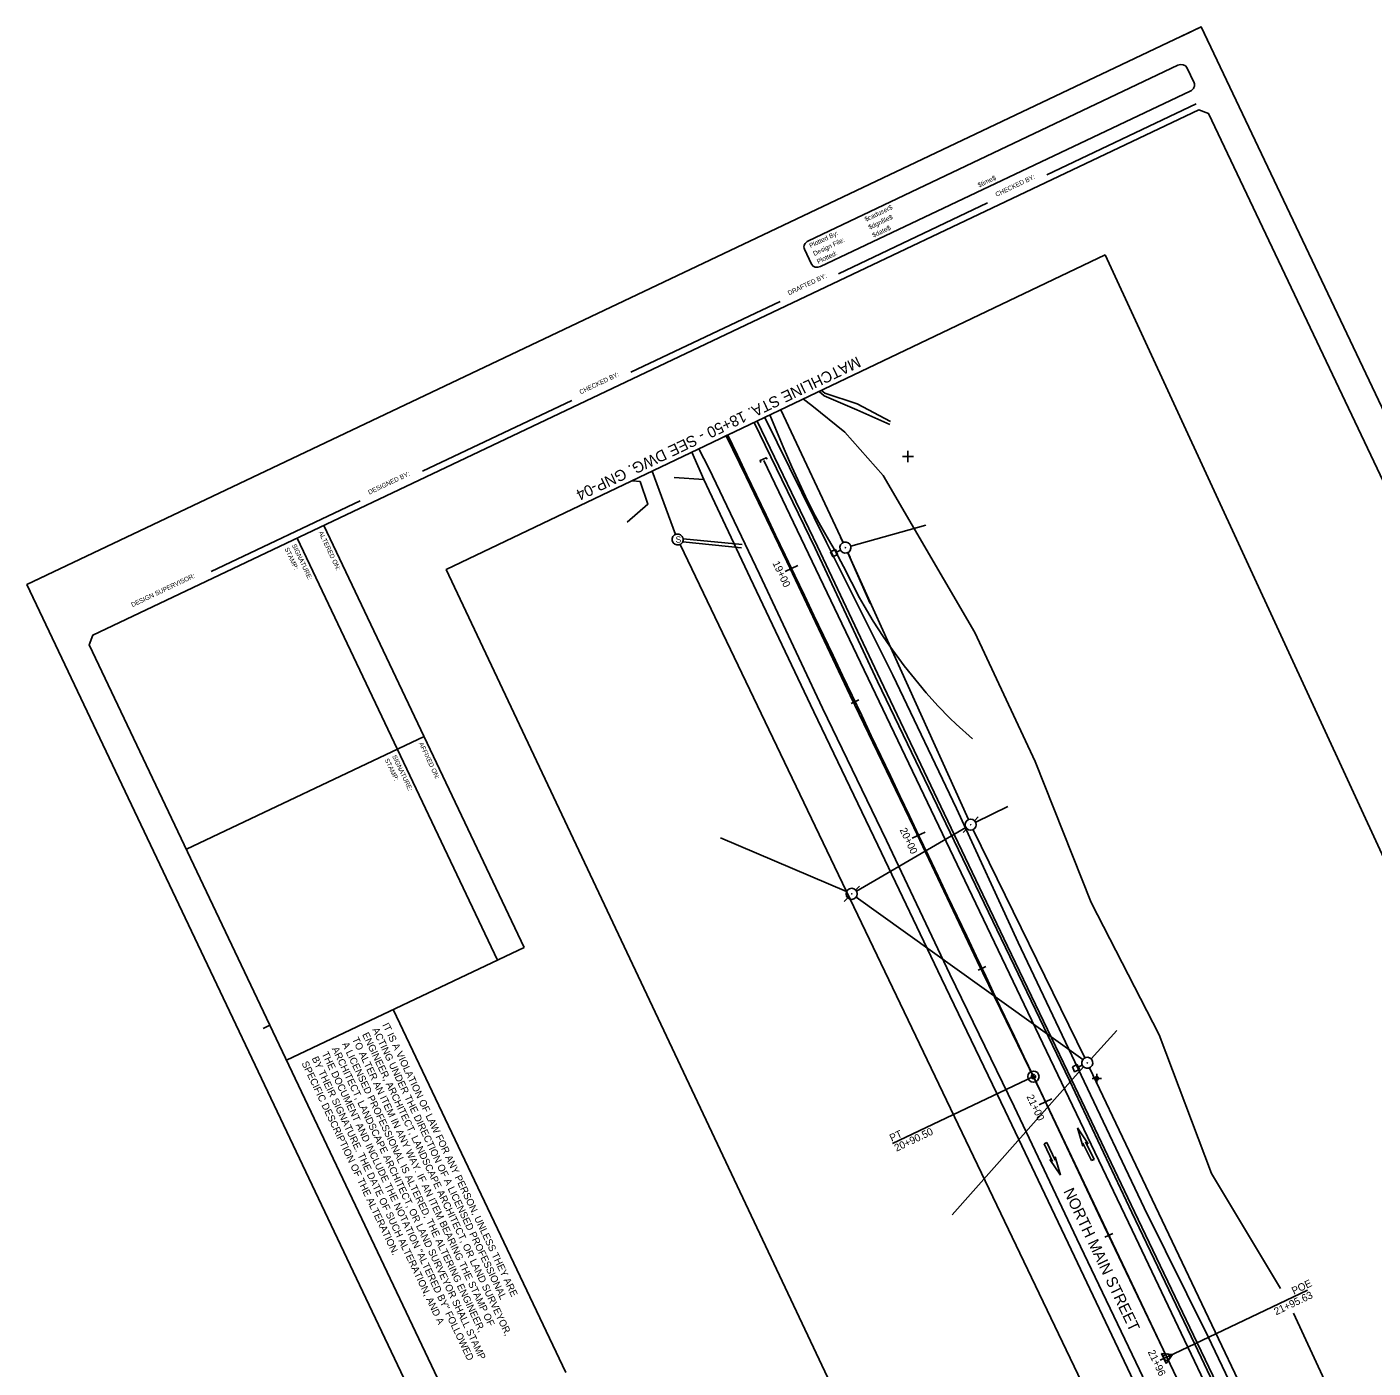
# Model space of a CAD drawing. Extents: x 1041072 to 1041761, y 1125784 to 1126587.
# Drawn here: x 1041071.6 to 1041527.2, y 1126132.8 to 1126586.8 of the extents above; entities that cross this region are included whole.
import ezdxf

# ---------------------------------------------------------------- set-up
doc = ezdxf.new("R2010")
doc.units = 0
for name, color, linetype in [('AC_P', 7, 'Continuous'), ('ACP_P', 7, 'Continuous'), ('ACSC_P_T', 7, 'Continuous'), ('ACSCT_P', 7, 'Continuous'), ('ACSR_P_T', 7, 'Continuous'), ('ACSRT_P', 7, 'Continuous'), ('clip boundary', 7, 'Continuous'), ('Default', 7, 'Continuous'), ('EWFG', 7, 'Continuous'), ('LAWA', 7, 'Continuous'), ('LAWE', 7, 'Continuous'), ('LELB', 7, 'Continuous'), ('NBS_P', 7, 'Continuous'), ('NBS_P_T', 7, 'Continuous'), ('NML_P', 7, 'Continuous'), ('NML_P_T', 7, 'Continuous'), ('O_Details_Text Title and Subtitle Proposed_P_T', 7, 'Continuous'), ('PE', 7, 'Continuous'), ('PELB', 7, 'Continuous'), ('PSU', 7, 'Continuous'), ('RGB', 7, 'Continuous'), ('S', 7, 'Continuous'), ('SHEET_BORDER', 7, 'Continuous'), ('SHEET_BORDER_CUT', 7, 'Continuous'), ('SHEET_BORDER_STAMPBOX', 7, 'Continuous'), ('SHEET_BORDER_TEXT', 7, 'Continuous'), ('STDSW', 7, 'Continuous'), ('STDSY', 7, 'Continuous'), ('STFBY', 7, 'Continuous'), ('STSEW', 7, 'Continuous'), ('STSEY_P_T', 7, 'Continuous'), ('UEO', 7, 'Continuous'), ('UG', 7, 'Continuous'), ('UP', 7, 'Continuous'), ('UPGW', 7, 'Continuous'), ('UPL', 7, 'Continuous'), ('USA', 7, 'Continuous'), ('USMH', 7, 'Continuous')]:
    doc.layers.add(name, color=color, linetype=linetype)

msp = doc.modelspace()

# ---------------------------------------------------------------- linework, layer by layer
at = {"layer": 'AC_P'}
msp.add_line((1041412.24, 1126231.51), (1041457.34, 1126136.54), dxfattribs=at)
msp.add_arc((951081.07, 1083333.02), 100000, 25.4031549, 25.5409537, dxfattribs=at)
at = {"layer": 'ACP_P'}
for centre, radius in [((1041412.24, 1126231.5), 1.89), ((1041412.24, 1126231.5), 0.744), ((1041412.24, 1126231.5), 0.154), ((1041457.34, 1126136.54), 1.09)]:
    msp.add_circle(centre, radius, dxfattribs=at)
at = {"layer": 'ACSCT_P'}
for points in [[(1041412.24, 1126231.51), (1041364.55, 1126208.86)], [(1041457.34, 1126136.54), (1041505.03, 1126159.19)]]:
    msp.add_lwpolyline(points, dxfattribs=at)
at = {"layer": 'ACSRT_P'}
for points in [[(1041310.11, 1126449.25), (1041307.51, 1126448.01)], [(1041332.52, 1126404.55), (1041328.19, 1126402.48)], [(1041353.18, 1126359), (1041350.58, 1126357.76)], [(1041375.55, 1126314.27), (1041371.21, 1126312.21)], [(1041396.16, 1126268.71), (1041393.56, 1126267.47)], [(1041418.48, 1126223.96), (1041414.15, 1126221.9)], [(1041439.06, 1126178.38), (1041436.46, 1126177.15)], [(1041459.51, 1126137.57), (1041455.17, 1126135.51)], [(1041459.51, 1126137.57), (1041455.17, 1126135.51)]]:
    msp.add_lwpolyline(points, dxfattribs=at)
at = {"layer": 'clip boundary'}
for points in [[(1041469.06, 1126586.8), (1041760.77, 1125972.54), (1041363.32, 1125783.79), (1041071.61, 1126398.04)], [(1041436.47, 1126509.64), (1041674.33, 1125994.72), (1041455.4, 1125890.75), (1041213.53, 1126403.1)]]:
    msp.add_lwpolyline(points, close=True, dxfattribs=at)
at = {"layer": 'Default'}
for points in [[(1041455.54, 1126137.78), (1041459.31, 1126137.48)], [(1041457.16, 1126134.37), (1041455.54, 1126137.78)], [(1041459.31, 1126137.48), (1041457.16, 1126134.37)]]:
    msp.add_lwpolyline(points, dxfattribs=at)
at = {"layer": 'EWFG'}
for q in [(1041367.88, 1126441.37), (1041369.77, 1126443.26), (1041369.77, 1126439.49), (1041371.66, 1126441.37)]:
    msp.add_line((1041369.77, 1126441.37), q, dxfattribs=at)
at = {"layer": 'LAWA'}
for points in [[(1041361.35, 1126435.01), (1041348.4, 1126449.63), (1041337.22, 1126458.6), (1041334.37, 1126460.85)], [(1041495.9, 1126159.82), (1041472.51, 1126198.66), (1041454.84, 1126245.66), (1041431.75, 1126290.45), (1041412.8, 1126338.2), (1041392.46, 1126381.83), (1041361.35, 1126435.01)], [(1041539.1, 1126067.96), (1041517.71, 1126113.61), (1041500.26, 1126151.47)]]:
    msp.add_lwpolyline(points, dxfattribs=at)
at = {"layer": 'LAWE'}
msp.add_lwpolyline([(1041363.84, 1126453.24), (1041352.63, 1126459.16), (1041341.64, 1126462.81), (1041340.49, 1126463.77)], dxfattribs=at)
at = {"layer": 'LELB'}
for points in [[(1041361.35, 1126435.01), (1041348.4, 1126449.63), (1041337.22, 1126458.6), (1041334.37, 1126460.85)], [(1041363.62, 1126452.27), (1041352.49, 1126457.19), (1041341.47, 1126461.95), (1041339.73, 1126463.41)]]:
    msp.add_lwpolyline(points, dxfattribs=at)
at = {"layer": 'NBS_P'}
for p, q in [((1041461.14, 1126573.8), (1041336.07, 1126514.41)), ((1041466.61, 1126567.92), (1041464.18, 1126573.04)), ((1041340.22, 1126505.68), (1041465.28, 1126565.07)), ((1041334.73, 1126511.56), (1041337.14, 1126506.48))]:
    msp.add_line(p, q, dxfattribs=at)
for centre, major_axis, start_param, end_param in [((1041461.99, 1126572), (2.19, 1.04), 0, 1.570796), ((1041464.42, 1126566.88), (2.19, 1.04), 4.712389, 6.283185), ((1041336.93, 1126512.61), (-2.19, -1.04), 4.712389, 6.283185), ((1041339.34, 1126507.53), (-2.19, -1.04), 0, 1.570796)]:
    msp.add_ellipse(centre, major_axis=major_axis, ratio=0.825959, start_param=start_param, end_param=end_param, dxfattribs=at)
at = {"layer": 'NML_P'}
msp.add_line((1041213.53, 1126403.1), (1041436.47, 1126509.64), dxfattribs=at)
at = {"layer": 'O_Details_Text Title and Subtitle Proposed_P_T'}
for p, q in [((1041428.99, 1126207.9), (1041427.14, 1126214.11)), ((1041430.79, 1126208.76), (1041427.14, 1126214.11)), ((1041416.3, 1126208.96), (1041416.28, 1126208.95)), ((1041416.31, 1126208.94), (1041416.29, 1126208.93)), ((1041429.91, 1126209.44), (1041430.79, 1126208.76)), ((1041419.61, 1126204.33), (1041421.45, 1126198.12)), ((1041417.8, 1126203.47), (1041421.45, 1126198.12)), ((1041418.68, 1126202.78), (1041417.8, 1126203.47)), ((1041432.28, 1126203.29), (1041432.31, 1126203.3)), ((1041432.29, 1126203.27), (1041432.32, 1126203.28))]:
    msp.add_line(p, q, dxfattribs=at)
at = {"layer": 'PE'}
for points in [[(1041318.73, 1126453.38), (1041339.18, 1126410.88), (1041360.46, 1126365.77), (1041382, 1126320.57), (1041403.51, 1126275.65), (1041425.15, 1126230.52), (1041446.44, 1126185.77), (1041467.64, 1126141.33), (1041488.94, 1126096.97), (1041510.5, 1126052.22), (1041532.3, 1126008.11), (1041535.7, 1126004.98)], [(1041276.51, 1126433.2), (1041279.12, 1126432.88), (1041281.76, 1126425.23), (1041274.77, 1126419.18)], [(1041290.63, 1126434.29), (1041300.65, 1126433.59), (1041316.42, 1126400.34), (1041337.87, 1126354.98), (1041359.55, 1126309.83), (1041381.09, 1126264.65), (1041402.69, 1126219.9), (1041424.02, 1126175.16), (1041445.11, 1126130.68), (1041466.42, 1126086.34), (1041488.85, 1126042.05), (1041509.64, 1125997.41), (1041511.03, 1125994.1)]]:
    msp.add_lwpolyline(points, dxfattribs=at)
at = {"layer": 'PELB'}
msp.add_lwpolyline([(1041296.6, 1126442.8), (1041300.65, 1126433.59)], dxfattribs=at)
at = {"layer": 'PSU'}
msp.add_lwpolyline([(1041533.7, 1126007.23), (1041534.28, 1126010.3), (1041513.25, 1126053.33), (1041492.46, 1126099.13), (1041471.38, 1126143.37), (1041449.72, 1126187.11), (1041428.39, 1126232), (1041407.07, 1126276.87), (1041386.16, 1126322.29), (1041364.66, 1126367.32), (1041342.25, 1126412.26), (1041321.36, 1126454.63)], dxfattribs=at)
at = {"layer": 'RGB'}
msp.add_lwpolyline([(1041323.04, 1126455.44), (1041327.54, 1126444.65), (1041330.47, 1126437.89), (1041335.11, 1126427.88), (1041338.42, 1126421.33), (1041340.16, 1126418.09), (1041342.88, 1126413.3), (1041345.12, 1126409.49), (1041347.97, 1126404.21), (1041353.42, 1126393.51), (1041354.9, 1126390.84), (1041358.03, 1126385.6), (1041361.37, 1126380.49), (1041363.69, 1126377.14), (1041368.53, 1126370.58), (1041373.4, 1126364.42), (1041375.92, 1126361.42), (1041379.85, 1126357.04), (1041383.96, 1126352.85), (1041386.1, 1126350.83), (1041391.59, 1126345.78)], dxfattribs=at)
at = {"layer": 'S'}
for p, q in [((1041433.68, 1126232.48), (1041433.68, 1126229.33)), ((1041435.26, 1126230.9), (1041432.11, 1126230.9))]:
    msp.add_line(p, q, dxfattribs=at)
msp.add_circle((1041433.68, 1126230.9), 0.591, dxfattribs=at)
at = {"layer": 'SHEET_BORDER'}
for p, q in [((1041416.74, 1126536.74), (1041467.26, 1126560.73)), ((1041346.23, 1126503.26), (1041396.75, 1126527.25)), ((1041275.99, 1126469.9), (1041326.51, 1126493.89)), ((1041205.49, 1126436.41), (1041256, 1126460.4)), ((1041133.97, 1126402.45), (1041184.42, 1126426.41)), ((1041153.85, 1126248.9), (1041151.59, 1126247.83))]:
    msp.add_line(p, q, dxfattribs=at)
msp.add_lwpolyline([(1041364.16, 1125811.87), (1041360.83, 1125813.06), (1041092.72, 1126377.63), (1041093.9, 1126380.96), (1041468.21, 1126558.72), (1041471.54, 1126557.53), (1041739.66, 1125992.96), (1041738.47, 1125989.63)], close=True, dxfattribs=at)
at = {"layer": 'SHEET_BORDER_CUT'}
msp.add_lwpolyline([(1041071.61, 1126398.04), (1041363.32, 1125783.79), (1041760.77, 1125972.54), (1041469.06, 1126586.8)], close=True, dxfattribs=at)
for points in [[(1041462.68, 1126583.76), (1041469.06, 1126586.8), (1041472.1, 1126580.41)], [(1041074.64, 1126391.65), (1041071.61, 1126398.04), (1041077.99, 1126401.08)]]:
    msp.add_lwpolyline(points, dxfattribs=at)
at = {"layer": 'SHEET_BORDER_STAMPBOX'}
for p, q in [((1041230.9, 1126270.96), (1041163.06, 1126413.8)), ((1041172.1, 1126418.09), (1041239.93, 1126275.25)), ((1041125.56, 1126308.47), (1041206.01, 1126346.67)), ((1041239.93, 1126275.25), (1041159.48, 1126237.05)), ((1041253.98, 1126131.3), (1041195.61, 1126254.21))]:
    msp.add_line(p, q, dxfattribs=at)
at = {"layer": 'STDSW'}
msp.add_lwpolyline([(1041299.01, 1126443.95), (1041302.38, 1126437.42)], dxfattribs=at)
at = {"layer": 'STDSY'}
msp.add_lwpolyline([(1041308.28, 1126448.38), (1041315.03, 1126434.56)], dxfattribs=at)
at = {"layer": 'STFBY'}
msp.add_lwpolyline([(1041315.03, 1126434.56), (1041328.74, 1126405.86), (1041350.24, 1126360.44), (1041371.73, 1126315.84), (1041393.22, 1126270.54), (1041414.86, 1126225.98), (1041436.23, 1126180.87), (1041457.34, 1126136.54), (1041478.55, 1126091.98), (1041500.21, 1126047.1), (1041521.3, 1126002.8), (1041523.32, 1125999.06)], dxfattribs=at)
at = {"layer": 'STSEW'}
for points in [[(1041317.78, 1126452.92), (1041338.32, 1126410.39), (1041359.47, 1126365.26), (1041381.18, 1126320.24), (1041402.77, 1126275.23), (1041424.41, 1126230.21), (1041445.57, 1126185.45), (1041466.81, 1126140.88), (1041487.94, 1126096.5), (1041509.48, 1126051.7), (1041530.7, 1126007.35), (1041533.35, 1126002.05)], [(1041302.38, 1126437.42), (1041319.49, 1126401.59), (1041340.82, 1126356.16), (1041362.55, 1126311.39), (1041383.93, 1126266.18), (1041405.7, 1126221.42), (1041426.91, 1126176.63), (1041448.11, 1126132.19), (1041469.24, 1126087.74), (1041490.67, 1126043.08), (1041511.89, 1125998.57), (1041513.9, 1125994.96)]]:
    msp.add_lwpolyline(points, dxfattribs=at)
at = {"layer": 'STSEY_P_T'}
for p, q in [((1041430.79, 1126208.76), (1041427.14, 1126214.11)), ((1041427.14, 1126214.11), (1041428.99, 1126207.9)), ((1041416.76, 1126209.17), (1041415.85, 1126208.75)), ((1041415.85, 1126208.75), (1041418.68, 1126202.78)), ((1041415.85, 1126208.75), (1041418.68, 1126202.78)), ((1041416.76, 1126209.17), (1041419.59, 1126203.21)), ((1041419.59, 1126203.21), (1041416.76, 1126209.17)), ((1041429.01, 1126209.02), (1041428.99, 1126207.9)), ((1041428.99, 1126207.9), (1041429.01, 1126209.02)), ((1041431.84, 1126203.05), (1041429.01, 1126209.02)), ((1041429.01, 1126209.02), (1041431.84, 1126203.05)), ((1041432.74, 1126203.48), (1041429.91, 1126209.44)), ((1041432.74, 1126203.48), (1041429.91, 1126209.44)), ((1041429.91, 1126209.44), (1041430.79, 1126208.76)), ((1041419.59, 1126203.21), (1041419.61, 1126204.33)), ((1041419.61, 1126204.33), (1041419.59, 1126203.21)), ((1041421.45, 1126198.12), (1041419.61, 1126204.33)), ((1041418.68, 1126202.78), (1041417.8, 1126203.47)), ((1041417.8, 1126203.47), (1041421.45, 1126198.12)), ((1041431.84, 1126203.05), (1041432.74, 1126203.48))]:
    msp.add_line(p, q, dxfattribs=at)
for points in [[(1041416.76, 1126209.17), (1041416.3, 1126208.96), (1041415.85, 1126208.75)], [(1041431.84, 1126203.05), (1041432.29, 1126203.27), (1041432.74, 1126203.48)]]:
    msp.add_lwpolyline(points, dxfattribs=at)
at = {"layer": 'UEO'}
for points in [[(1041326.75, 1126457.21), (1041347.82, 1126412.24)], [(1041350.43, 1126411.04), (1041375.81, 1126418.11)], [(1041349.39, 1126408.82), (1041390.23, 1126318.49)], [(1041352.38, 1126294.31), (1041389.38, 1126315.82)], [(1041391.84, 1126315.07), (1041429.63, 1126237.85)], [(1041306.31, 1126312.36), (1041348.94, 1126294.13)], [(1041352.28, 1126292.26), (1041428.93, 1126237.26)], [(1041384.78, 1126184.7), (1041429.21, 1126234.76)], [(1041431.27, 1126234.47), (1041511.79, 1126065.26)]]:
    msp.add_lwpolyline(points, dxfattribs=at)
at = {"layer": 'UG'}
for points in [[(1041319.99, 1126439.4), (1041319.72, 1126439.98), (1041321.83, 1126440.98), (1041322.08, 1126440.46)], [(1041321.05, 1126439.99), (1041445.71, 1126179.57), (1041490.03, 1126086.37), (1041561.51, 1125941.15)]]:
    msp.add_lwpolyline(points, dxfattribs=at)
at = {"layer": 'UP'}
for p, q in [((1041392.35, 1126318.11), (1041393.59, 1126319.37)), ((1041389.68, 1126315.43), (1041388.43, 1126314.17)), ((1041391.08, 1126316.77), (1041390.95, 1126316.77)), ((1041391.01, 1126316.83), (1041391.01, 1126316.71)), ((1041352.08, 1126294.71), (1041353.33, 1126295.96)), ((1041349.41, 1126292.02), (1041348.16, 1126290.77)), ((1041350.81, 1126293.36), (1041350.68, 1126293.36)), ((1041350.74, 1126293.43), (1041350.74, 1126293.3))]:
    msp.add_line(p, q, dxfattribs=at)
for centre in [(1041391.01, 1126316.77), (1041350.74, 1126293.36)]:
    msp.add_circle(centre, 1.89, dxfattribs=at)
at = {"layer": 'UPGW'}
for points in [[(1041357.01, 1126391.6), (1041349.38, 1126408.82)], [(1041403.53, 1126322.9), (1041392.71, 1126317.6)], [(1041440.51, 1126247.14), (1041431.73, 1126237.55)]]:
    msp.add_lwpolyline(points, dxfattribs=at)
at = {"layer": 'UPL'}
for p, q in [((1041346.98, 1126413.92), (1041347.8, 1126412.23)), ((1041345.59, 1126409.06), (1041346.93, 1126409.71)), ((1041348.51, 1126410.57), (1041348.73, 1126410.5)), ((1041348.58, 1126410.42), (1041348.66, 1126410.65)), ((1041349.44, 1126408.84), (1041350.26, 1126407.15)), ((1041428.87, 1126239.57), (1041429.66, 1126237.87)), ((1041430.35, 1126236.2), (1041430.57, 1126236.12)), ((1041430.42, 1126236.05), (1041430.5, 1126236.27)), ((1041427.41, 1126234.73), (1041428.76, 1126235.36)), ((1041431.25, 1126234.46), (1041432.05, 1126232.76))]:
    msp.add_line(p, q, dxfattribs=at)
for points in [[(1041343.6, 1126409.08), (1041344.37, 1126407.48), (1041345.98, 1126408.26), (1041345.2, 1126409.86)], [(1041425.41, 1126234.78), (1041426.17, 1126233.16), (1041427.79, 1126233.92), (1041427.03, 1126235.54)]]:
    msp.add_lwpolyline(points, close=True, dxfattribs=at)
for centre, major_axis in [((1041348.62, 1126410.54), (0.93, 1.63)), ((1041430.46, 1126236.16), (0.95, 1.62))]:
    msp.add_ellipse(centre, major_axis=major_axis, ratio=0.998335, dxfattribs=at)
at = {"layer": 'USA'}
for p, q in [((1041283.18, 1126436.39), (1041291.16, 1126415.04)), ((1041292.63, 1126411.58), (1041468.13, 1126045.57)), ((1041293.53, 1126412.45), (1041313.47, 1126410.48)), ((1041293.71, 1126413.53), (1041313.66, 1126411.56))]:
    msp.add_line(p, q, dxfattribs=at)
at = {"layer": 'USMH'}
msp.add_ellipse((1041291.84, 1126413.29), major_axis=(1.07, -1.55), ratio=0.998335, dxfattribs=at)

# ---------------------------------------------------------------- texts
at = {"layer": 'ACSC_P_T'}
for s, p in [('PT', (1041364.28, 1126209.42)), ('20+90.50', (1041365.88, 1126206.04)), ('21+95.63', (1041494.37, 1126150.68)), ('POE', (1041500.37, 1126157.67))]:
    msp.add_text(s, height=2.496, rotation=25.4032, dxfattribs=at).set_placement(p)
at = {"layer": 'ACSR_P_T'}
for s, rotation, p in [('19+00', 295.5123, (1041323.86, 1126405.3)), ('20+00', 295.455, (1041366.89, 1126315.03)), ('21+00', 295.4032, (1041409.83, 1126224.72)), ('21+96', 295.4032, (1041450.87, 1126138.31)), ('21+96', 295.4032, (1041450.87, 1126138.31))]:
    msp.add_text(s, height=2.496, rotation=rotation, dxfattribs=at).set_placement(p)
at = {"layer": 'NBS_P_T'}
for s, height, p in [('$time$', 1.576, (1041393.86, 1126532.4)), ('$caduser$', 1.576, (1041355.54, 1126520.84)), ('$dgnfile$', 1.576, (1041356.83, 1126518.13)), ('$date$', 1.576, (1041358.11, 1126515.43)), ('Plotted By:', 1.5759, (1041336.82, 1126511.95)), ('Design File:', 1.5759, (1041338.11, 1126509.24)), ('Plotted:', 1.576, (1041339.39, 1126506.54))]:
    msp.add_text(s, height=height, rotation=25.4036, dxfattribs=at).set_placement(p)
at = {"layer": 'NML_P_T'}
msp.add_text('MATCHLINE STA. 18+50 - SEE DWG. GNP-04', height=3.744, rotation=205.541, dxfattribs=at).set_placement((1041352.61, 1126475.37))
at = {"layer": 'O_Details_Text Title and Subtitle Proposed_P_T'}
msp.add_text('NORTH MAIN STREET', height=3.7536, rotation=295.4032, dxfattribs=at).set_placement((1041422.28, 1126192.71))
at = {"layer": 'SHEET_BORDER_STAMPBOX'}
for s, height, p in [('ALTERED ON:', 1.5625, (1041170.28, 1126415.63)), ('STAMP:', 1.562, (1041158.74, 1126410.15)), ('SIGNATURE:', 1.562, (1041161.25, 1126411.34)), ('AFFIXED ON:', 1.5625, (1041204.2, 1126344.21)), ('STAMP:', 1.562, (1041192.66, 1126338.73)), ('SIGNATURE:', 1.562, (1041195.17, 1126339.92)), ('IT IS A VIOLATION OF LAW FOR ANY PERSON, UNLESS THEY ARE ', 2.4, (1041191.83, 1126249.02)), ('TO ALTER AN ITEM IN ANY WAY. IF AN ITEM BEARING THE STAMP OF ', 2.4, (1041181.58, 1126244.16)), ('ENGINEER, ARCHITECT, LANDSCAPE ARCHITECT, OR LAND SURVEYOR, ', 2.4, (1041185, 1126245.78)), ('ACTING UNDER THE DIRECTION OF A LICENSED PROFESSIONAL ', 2.4, (1041188.41, 1126247.4)), ('ARCHITECT, LANDSCAPE ARCHITECT, OR LAND SURVEYOR SHALL STAMP ', 2.4, (1041174.75, 1126240.91)), ('A LICENSED PROFESSIONAL IS ALTERED, THE ALTERING ENGINEER, ', 2.4, (1041178.17, 1126242.53)), ('SPECIFIC DESCRIPTION OF THE ALTERATION.', 2.4, (1041164.5, 1126236.04)), ('BY THEIR SIGNATURE. THE DATE OF SUCH ALTERATION, AND A ', 2.4, (1041167.92, 1126237.67)), ('THE DOCUMENT AND INCLUDE THE NOTATION "ALTERED BY" FOLLOWED ', 2.4, (1041171.33, 1126239.29))]:
    msp.add_text(s, height=height, rotation=295.4032, dxfattribs=at).set_placement(p)
at = {"layer": 'SHEET_BORDER_TEXT'}
for s, p in [('CHECKED BY:', (1041399.78, 1126529.26)), ('DRAFTED BY:', (1041329.54, 1126495.9)), ('CHECKED BY:', (1041259.03, 1126462.42)), ('DESIGNED BY:', (1041187.51, 1126428.45)), ('DESIGN SUPERVISOR:', (1041107.32, 1126390.37))]:
    msp.add_text(s, height=1.5625, rotation=25.4032, dxfattribs=at).set_placement(p)
at = {"layer": 'USMH'}
msp.add_text('S', height=2.15, rotation=360, dxfattribs=at).set_placement((1041291.13, 1126412.21))

doc.saveas('drawing.dxf')
